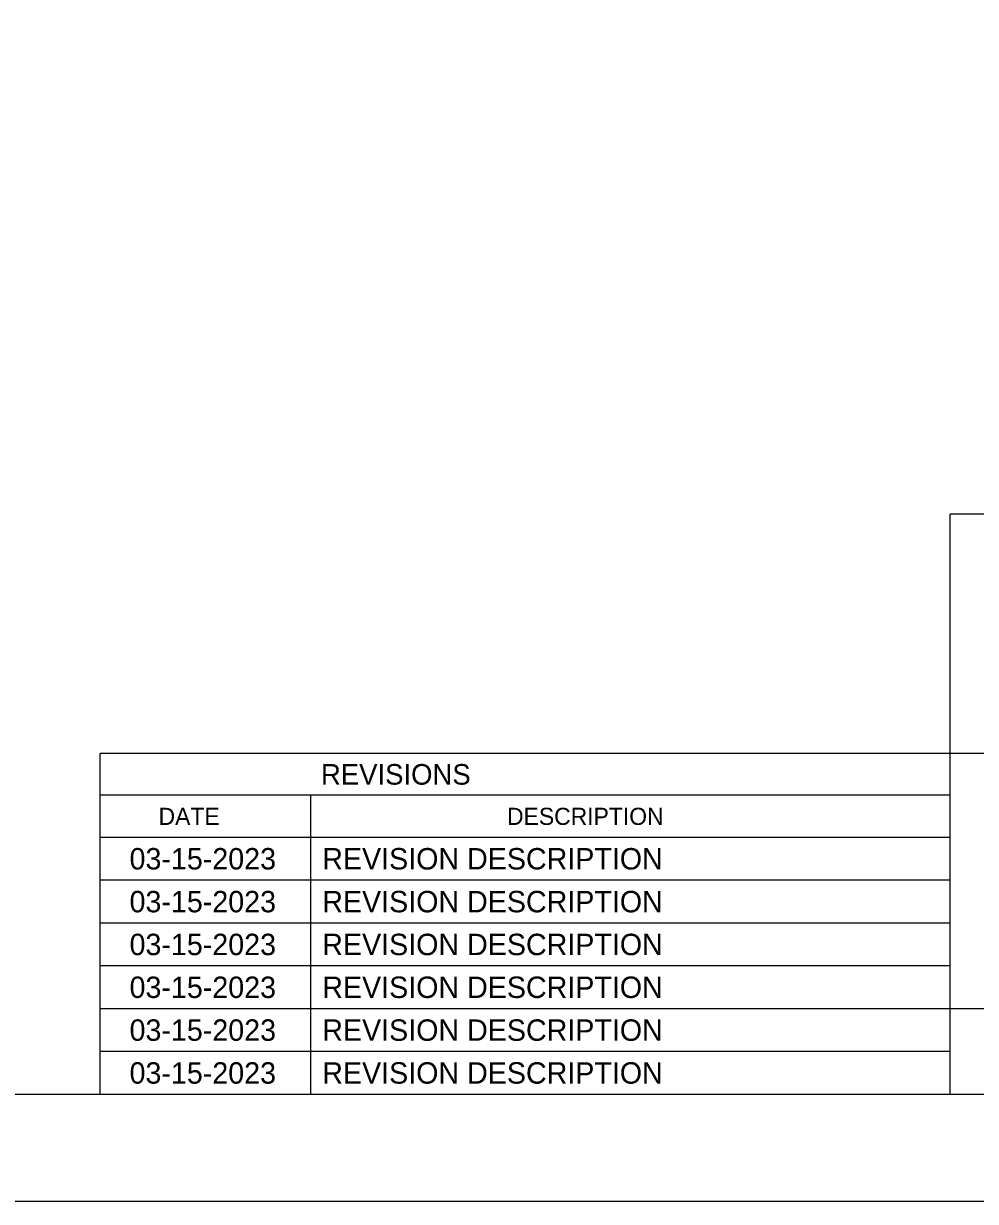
# Model space of a CAD drawing. Extents: x -0.22 to 2.83, y -0.07 to 1.83.
# Drawn here: x 2.071 to 2.4415, y 0 to 0.4583 of the extents above; entities that cross this region are included whole.
import ezdxf

# ---------------------------------------------------------------- set-up
doc = ezdxf.new("R2010")
doc.units = 0
for name, color, linetype in [('SH_General_Details', 7, 'Continuous'), ('SH_General_Details_Sheet_Revision_Box-ILTollway', 7, 'Continuous'), ('SH_General_Details_Sheet_Revision_Text-ILTollway', 7, 'Continuous'), ('SH_Printer Plotting Border-ILTollway', 7, 'Continuous')]:
    doc.layers.add(name, color=color, linetype=linetype)

msp = doc.modelspace()

# ---------------------------------------------------------------- linework, layer by layer
at = {"layer": 'SH_General_Details'}
for p, q in [((2.43167, 0.04167), (2.43167, 0.2674)), ((2.79167, 0.2674), (2.43167, 0.2674)), ((2.79167, 0.17434), (2.43167, 0.17434)), ((2.79167, 0.075), (2.43167, 0.075))]:
    msp.add_line(p, q, dxfattribs=at)
msp.add_lwpolyline([(0.16667, 0.04167), (0.16667, 1.79167), (2.79167, 1.79167), (2.79167, 0.04167)], close=True, dxfattribs=at)
at = {"layer": 'SH_General_Details_Sheet_Revision_Box-ILTollway'}
for p, q in [((2.10084, 0.04167), (2.10084, 0.17434)), ((2.43167, 0.17434), (2.10084, 0.17434)), ((2.43167, 0.15802), (2.10084, 0.15802)), ((2.18272, 0.15802), (2.18272, 0.04167)), ((2.43167, 0.14167), (2.10084, 0.14167)), ((2.43167, 0.125), (2.10084, 0.125)), ((2.43167, 0.10833), (2.10084, 0.10833)), ((2.43167, 0.09167), (2.10084, 0.09167)), ((2.43167, 0.075), (2.10084, 0.075)), ((2.43167, 0.05833), (2.10084, 0.05833))]:
    msp.add_line(p, q, dxfattribs=at)
at = {"layer": 'SH_Printer Plotting Border-ILTollway'}
msp.add_lwpolyline([(0, 1.83328), (2.83333, 1.83328), (2.83333, 0), (0, 0)], close=True, dxfattribs=at)

# ---------------------------------------------------------------- texts
at = {"layer": 'SH_General_Details_Sheet_Revision_Box-ILTollway'}
for s, height, p in [('REVISIONS', 0.008, (2.18678, 0.16218)), ('DATE', 0.006667, (2.12358, 0.14651)), ('DESCRIPTION', 0.0066667, (2.25919, 0.14651))]:
    msp.add_text(s, height=height, rotation=0, dxfattribs=at).set_placement(p)
at = {"layer": 'SH_General_Details_Sheet_Revision_Text-ILTollway'}
for s, height, p in [('03-15-2023', 0.008333, (2.11229, 0.12917)), ('REVISION DESCRIPTION', 0.0083333, (2.18729, 0.12917)), ('03-15-2023', 0.008333, (2.11229, 0.1125)), ('REVISION DESCRIPTION', 0.0083333, (2.18729, 0.1125)), ('03-15-2023', 0.008333, (2.11229, 0.09583)), ('REVISION DESCRIPTION', 0.0083333, (2.18729, 0.09583)), ('03-15-2023', 0.008333, (2.11229, 0.07917)), ('REVISION DESCRIPTION', 0.0083333, (2.18729, 0.07917)), ('03-15-2023', 0.008333, (2.11229, 0.0625)), ('REVISION DESCRIPTION', 0.0083333, (2.18729, 0.0625)), ('03-15-2023', 0.008333, (2.11229, 0.04583)), ('REVISION DESCRIPTION', 0.0083333, (2.18729, 0.04583))]:
    msp.add_text(s, height=height, dxfattribs=at).set_placement(p)

doc.saveas('drawing.dxf')
